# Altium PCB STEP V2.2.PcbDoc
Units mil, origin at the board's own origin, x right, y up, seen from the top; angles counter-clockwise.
Board outline 2047.24 x 720 mil, 4 copper layers (Top Layer, Signal Layer 1, Signal Layer 2, Bottom Layer), stack 30.634 mil thick; 93 components, 117 nets, 440 pads, 136 vias.
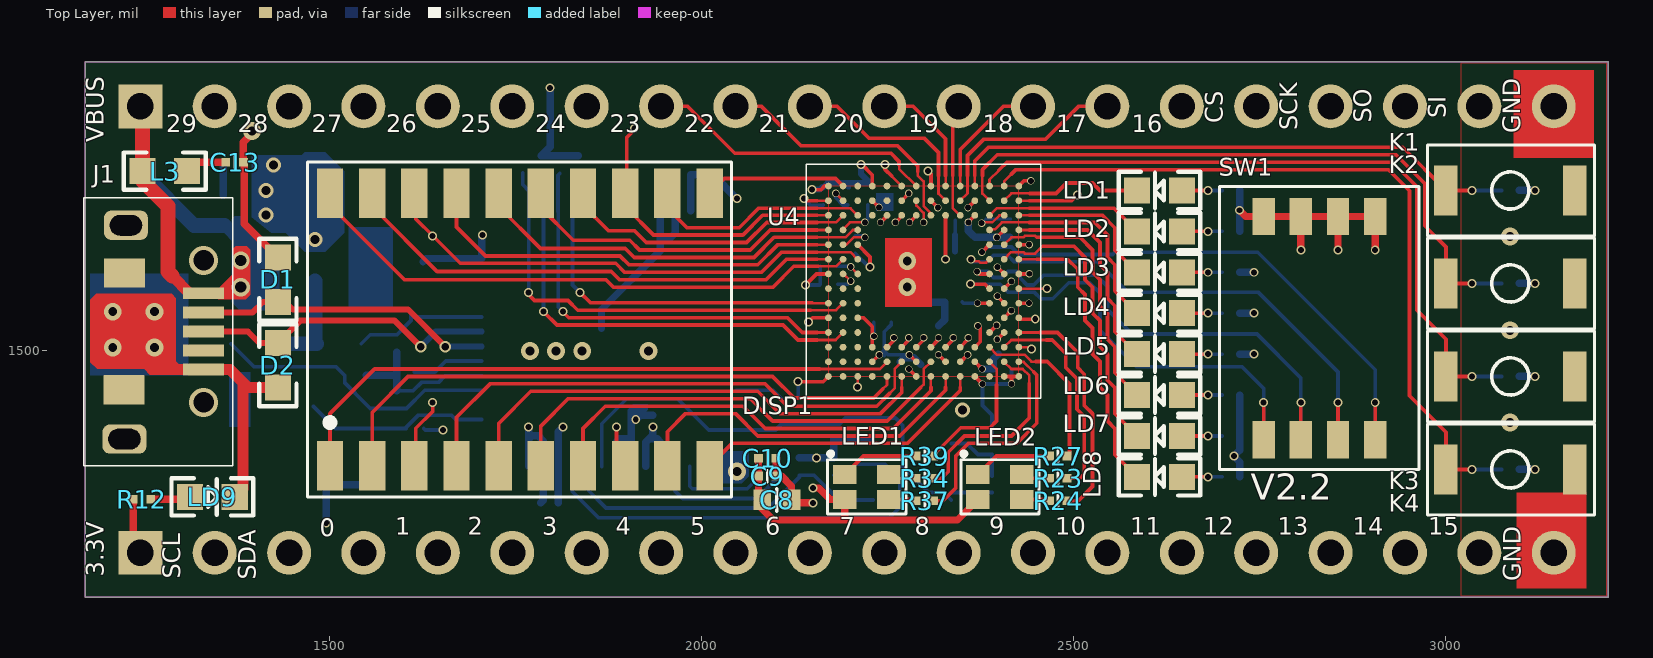
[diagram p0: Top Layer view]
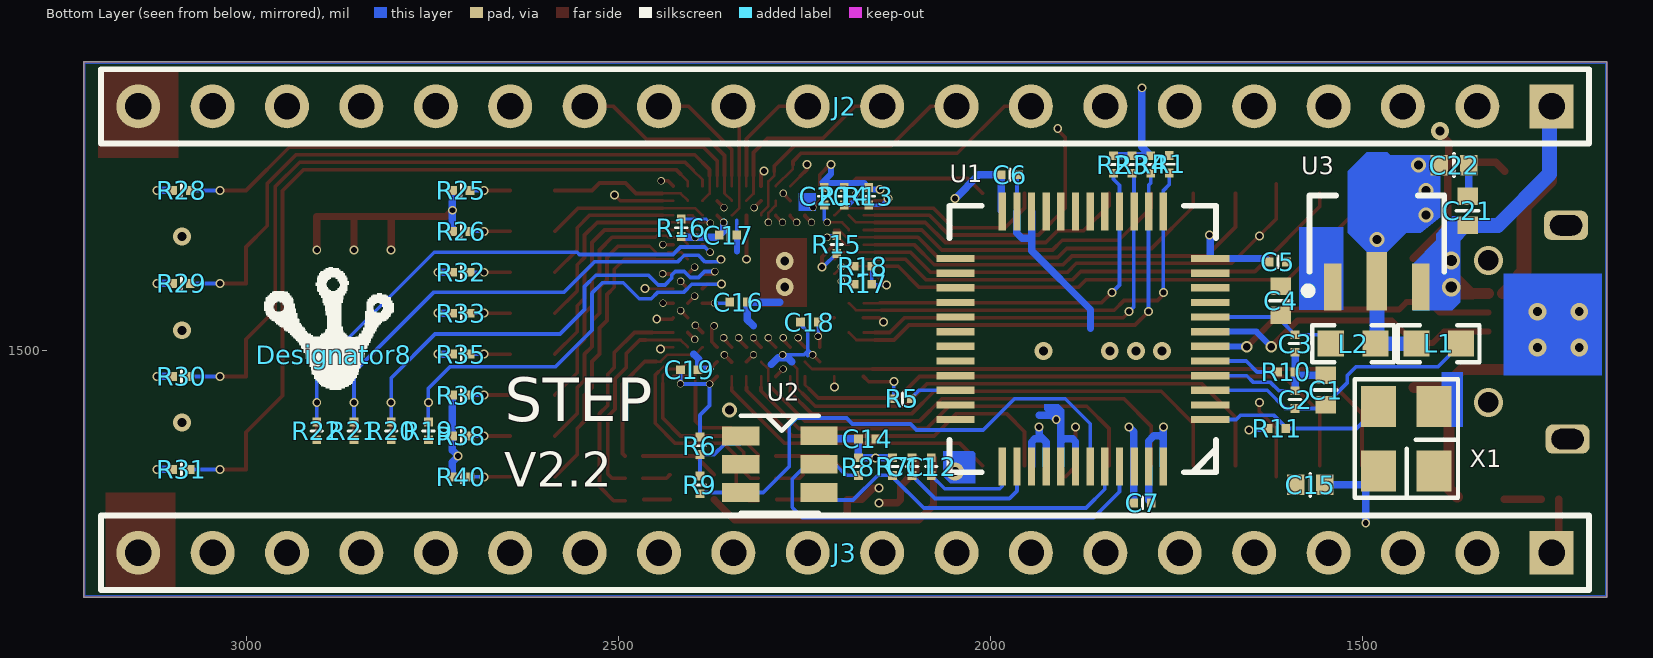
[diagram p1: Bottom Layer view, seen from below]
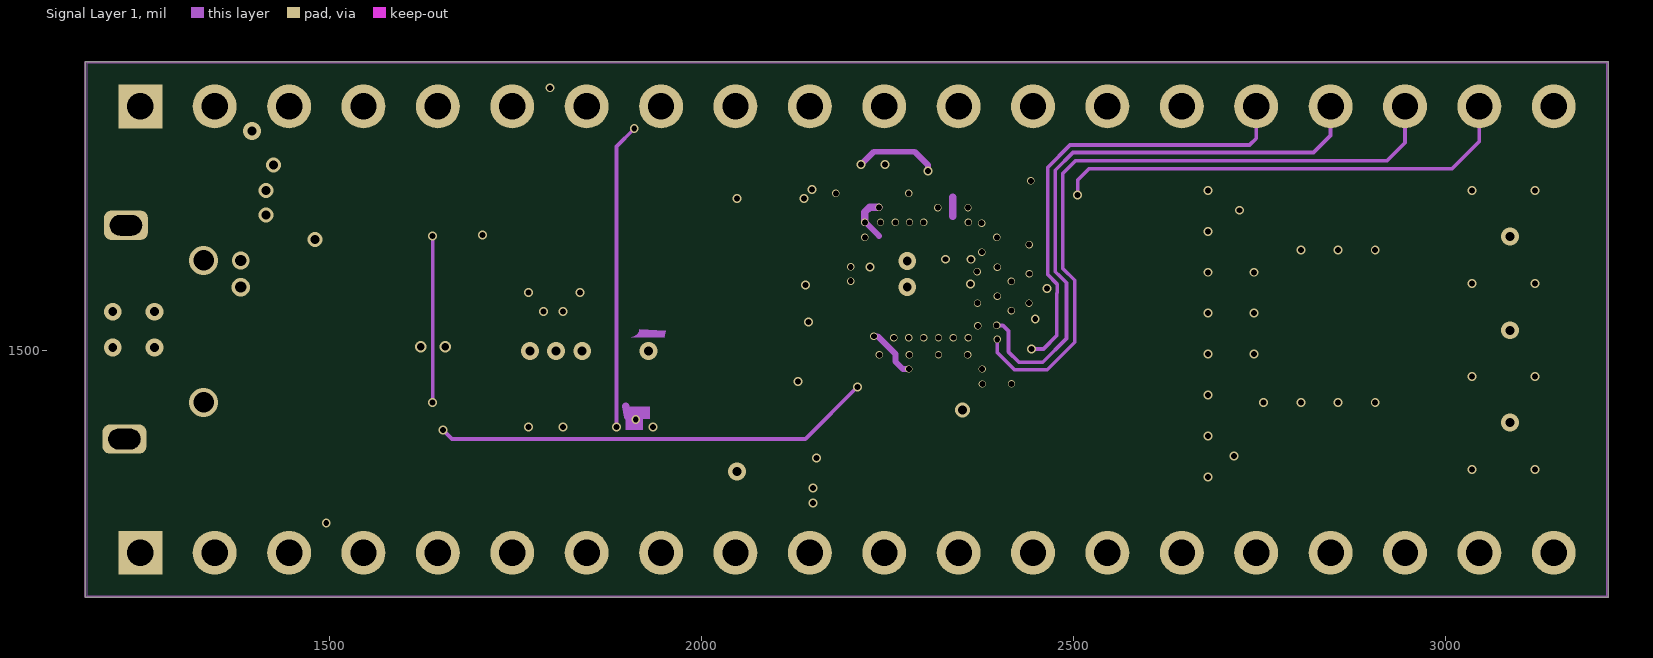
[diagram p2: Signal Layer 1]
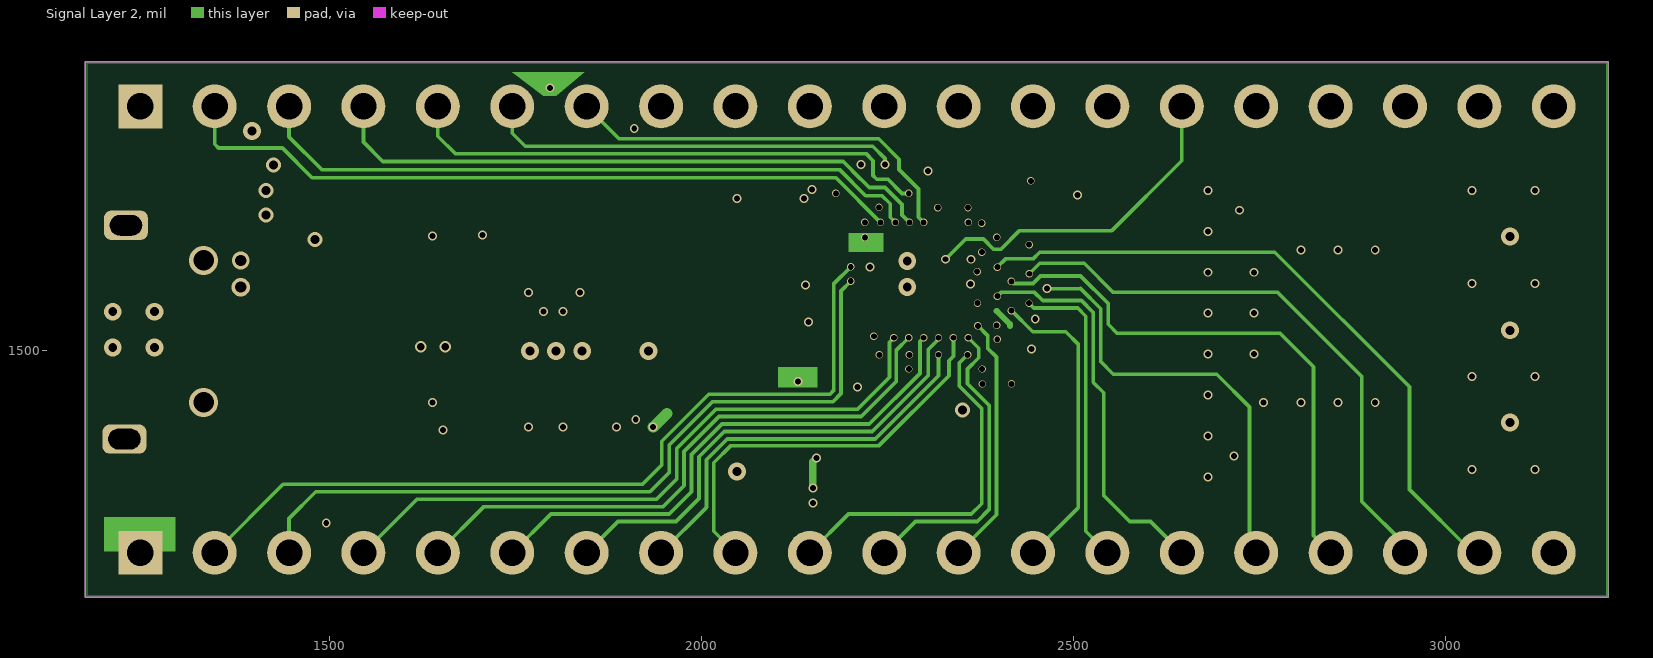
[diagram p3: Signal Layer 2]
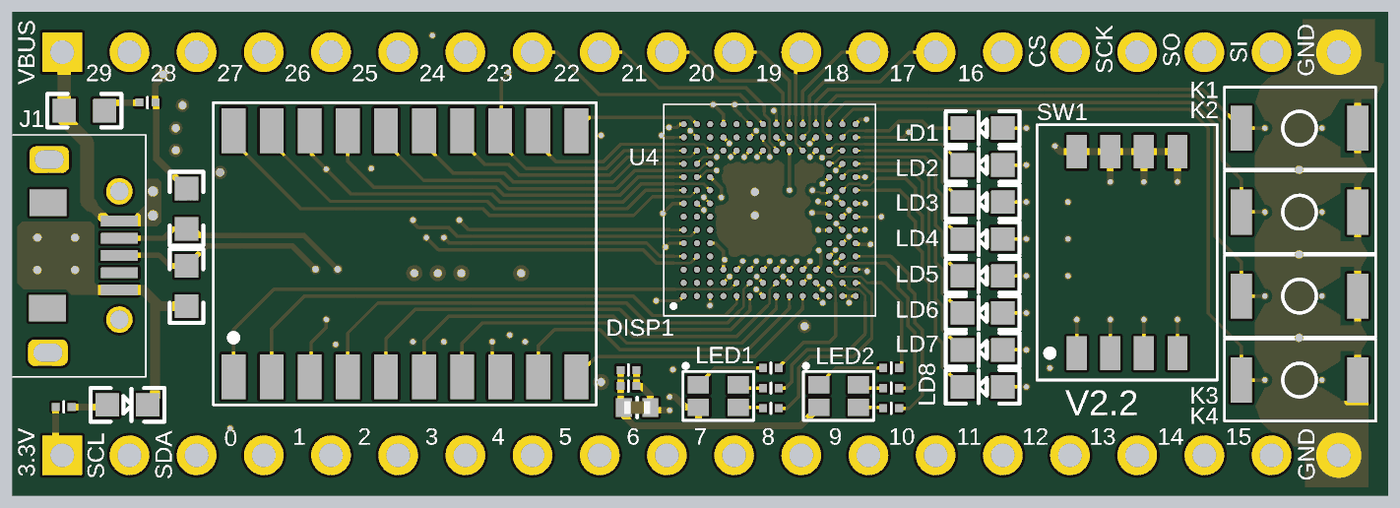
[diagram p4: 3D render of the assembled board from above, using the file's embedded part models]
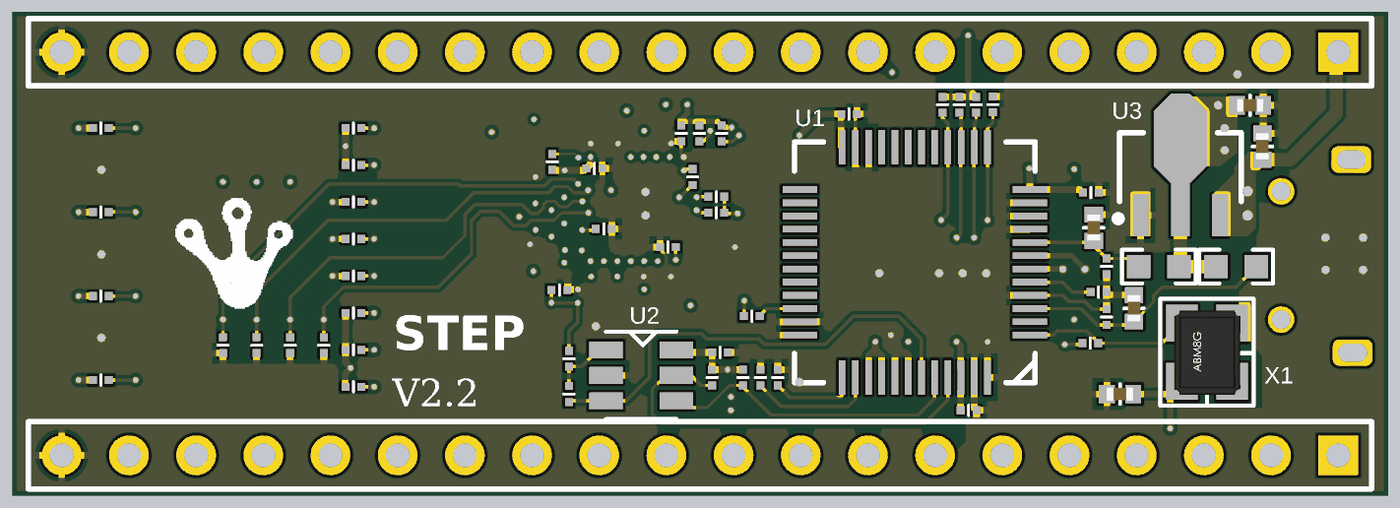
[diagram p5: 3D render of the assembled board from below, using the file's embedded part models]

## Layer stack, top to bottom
Top Solder: solder mask 0.4, Solder Resist, Dk 3.5
Top Layer: signal copper 1.4
Dielectric 1: core 10, FR-4, Dk 4.2
Signal Layer 1: signal copper 1.417
Dielectric 3: prepreg 5, Dk 4.2
Signal Layer 2: signal copper 1.417
Dielectric 2: core 10, Dk 4.2
Bottom Layer: signal copper 1.4
Bottom Solder: solder mask 0.4, Solder Resist, Dk 3.5

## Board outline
1171,1168 1171,1888 3218.24,1888 3218.24,1168

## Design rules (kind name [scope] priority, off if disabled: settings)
Clearance [All] p1: gap=3
ComponentClearance [All] p1: gap=0 collisioncheckmode=3 verticalgap=0 showdistances=FALSE
HoleToHoleClearance [All] p1: gap=8 allowstackedmicrovias=TRUE
MinimumSolderMaskSliver [All] p1: minsoldermaskwidth=0
PlaneClearance [All] p1: clearance=10
PolygonConnect PolygonConnect_1 [isvia] p1: connectstyle=Direct reliefconductorwidth=10 reliefentries=4 polygonreliefangle="90 Angle" airgapwidth=10
PolygonConnect [All] p2: connectstyle=Relief reliefconductorwidth=10 reliefentries=4 polygonreliefangle="90 Angle" airgapwidth=10
RoutingVias [All] p1: holewidth=12 width=24 viastyle="Through Hole" minholewidth=8 minwidth=10 maxholewidth=100 maxwidth=200
SilkToSilkClearance [All] p1: silktosilkclearance=0
SilkToSolderMaskClearance [IsPad] p1: minsilkscreentomaskgap=0 clearancetoexposedcopper=TRUE
SolderMaskExpansion [All] p1: expansion=4
Width [All] p1: maxlimit=100 minlimit=3 preferedwidth=5
24 further rules are at their usual default settings.

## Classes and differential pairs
component class "STEP V2.1.0": C1 C2 C3 C4 C5 C6 C7 C8 C9 C10 C11 C12 C13 C14 C15 C16 C17 C18 C19 C20 C21 C22 D1 D2 J1 L1 L2 L3 LD9 R1 R2 R3 R4 R5 R6 R7 R8 R9 R10 R11 R12 U1 U2 U3 X1
component class "STEP V2.1.1": DISP1 J2 J3 K1 K2 K3 K4 LD1 LD2 LD3 LD4 LD5 LD6 LD7 LD8 LED1 LED2 R13 R14 R15 R16 R17 R18 R19 R20 R21 R22 R23 R24 R25 R26 R27 R28 R29 R30 R31 R32 R33 R34 R35 R36 R37 R38 R39 R40 SW1 U4

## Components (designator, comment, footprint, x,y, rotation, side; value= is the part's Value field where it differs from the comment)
C1 "4.7u" C0402 1549,1427 r90 bottom
C2 "0.1u" C0201 1590,1422 r90 bottom
C3 "0.1u" C0201 1590,1521 r270 bottom
C4 "4.7u" C0402 1609,1547 r90 bottom
C5 "0.1u" C0201 1625,1619 r180 bottom
C6 "0.1u" C0201 1985,1736 r180 bottom
C7 "0.1u" C0201 1807,1295 r180 bottom
C8 "4.7u" C0402 2081,1299 r0 top
C9 "0.1u" C0201 2076,1331 r0 top
C10 "0.1u" C0201 2076,1355 r0 top
C11 "0.1u" C0201 2105,1332 r90 bottom
C12 "0.1u" C0201 2079,1332 r90 bottom
C13 "0.01u" C0201 1360,1753 r0 top
C14 "0.1u" C0201 2177,1381 r180 bottom
C15 "0.1u" C0402 1549.98,1319.17 r0 bottom
C16 "0.1u" C0201 2350,1565 r180 bottom
C17 "0.1u" C0201 2364,1655 r180 bottom
C18 "0.1u" C0201 2231,1538 r0 bottom
C19 "0.1u" C0201 2416,1474 r180 bottom
C20 "0.1u" C0201 2223,1719 r270 bottom
C21 "2.2u" C0402 1358,1668 r90 bottom
C22 "2.2u" C0402 1396,1749 r180 bottom
D1 "PGB1010603" C0603 1430,1625 r270 top
D2 "PGB1010603" C0603 1430,1450 r90 top
Designator8 "Comment" ECBC-STEP-M 2882,1494 r180 bottom
DISP1 "DISP" SMD_LED_2*8BIT_10*14 1500,1345 r0 top
J1 "MicroUSB" MICRO_USB_4 1330,1430 r90 top
J2 "Header 20" HDR1X20 1245,1828 r0 bottom
J3 "Header 20" HDR1X20 1245,1228 r0 bottom
K1 "SW-PB" SMD_KEY_3x4x2 3000,1715 r0 top
K2 "SW-PB" SMD_KEY_3x4x2 3000,1590 r0 top
K3 "SW-PB" SMD_KEY_3x4x2 3000,1465 r0 top
K4 "SW-PB" SMD_KEY_3x4x2 3000,1340 r0 top
L1 "600R,0.5A" L0603 1427,1509 r180 bottom
L2 "600R,0.5A" L0603 1542,1509 r180 bottom
L3 "600R,0.5A" L0603 1308,1741 r180 top
LD1 "Red" LED0603 2645,1715 r180 top (schematic designator LD2)
LD2 "Red" LED0603 2645,1660 r180 top (schematic designator LD3)
LD3 "Red" LED0603 2645,1605 r180 top (schematic designator LD4)
LD4 "Red" LED0603 2645,1550 r180 top (schematic designator LD5)
LD5 "Red" LED0603 2645,1495 r180 top (schematic designator LD6)
LD6 "Red" LED0603 2645,1440 r180 top (schematic designator LD7)
LD7 "Red" LED0603 2645,1385 r180 top (schematic designator LD8)
LD8 "Red" LED0603 2645,1330 r180 top (schematic designator LD9)
LD9 "Green" LED0603 1312,1303 r0 top
LED1 "RGB_LED" SMD_RGB_LED_1.5*1.6 2192,1333 r0 top
LED2 "RGB_LED" SMD_RGB_LED_1.5*1.6 2371,1333 r0 top
R1 "4K7" R0201 1759,1762 r270 bottom
R2 "10K" R0201 1834,1738 r90 bottom
R3 "10K" R0201 1809,1738 r90 bottom
R4 "10K" R0201 1784,1738 r90 bottom
R5 "10K" R0201 2106,1435 r0 bottom
R6 "10K" R0201 2390,1360 r90 bottom
R7 "10K" R0201 2131,1332 r90 bottom
R8 "10K" R0201 2177,1332 r90 bottom
R9 "4K7" R0201 2390,1331 r270 bottom
R10 "12K 1%" R0201 1590,1471 r0 bottom
R11 "33R" R0201 1626,1395 r180 bottom
R12 "1K" R0201 1259,1300 r180 top
R13 "10K" R0201 2163,1719 r270 bottom
R14 "10K" R0201 2196,1719 r270 bottom
R15 "10K" R0201 2206,1654 r270 bottom
R16 "10K" R0201 2415,1653 r90 bottom
R17 "10K" R0201 2159,1589 r0 bottom
R18 "10K" R0201 2159,1613 r0 bottom
R19 "10K" R0201 2755,1380 r90 bottom
R20 "10K" R0201 2805,1380 r90 bottom
R21 "10K" R0201 2855,1380 r90 bottom
R22 "10K" R0201 2905,1380 r90 bottom
R23 "1K" R0201 2467,1328 r0 top
R24 "1K" R0201 2467,1298 r0 top
R25 "1K" R0201 2699,1715 r0 bottom
R26 "1K" R0201 2699,1660 r0 bottom
R27 "1K" R0201 2467,1358 r0 top
R28 "10K" R0201 3075,1715 r0 bottom
R29 "10K" R0201 3075,1590 r0 bottom
R30 "10K" R0201 3075,1465 r0 bottom
R31 "10K" R0201 3075,1340 r0 bottom
R32 "1K" R0201 2699,1605 r0 bottom
R33 "1K" R0201 2699,1550 r0 bottom
R34 "1K" R0201 2288,1328 r0 top
R35 "1K" R0201 2699,1495 r0 bottom
R36 "1K" R0201 2699,1440 r0 bottom
R37 "1K" R0201 2288,1298 r0 top
R38 "1K" R0201 2699,1385 r0 bottom
R39 "1K" R0201 2288,1358 r0 top
R40 "1K" R0201 2699,1330 r0 bottom
SW1 "SPST4" SMD_KEY_4 2755,1380 r0 top
U1 "FT232HQ" LQFP9*9_48 1704,1407 r0 bottom
U2 "93LC56B" SOT-23-6 2335,1347 r270 bottom
U3 "LT1117-3.3" SOT-89-1 1480,1660 r90 bottom
U4 "LCMXO2-4000HC-4MG132" CSBGA132 2170,1465 r90 top
X1 "12MHz" SMD_CLK_2.5X3.2X0.8 1403,1338 r90 bottom

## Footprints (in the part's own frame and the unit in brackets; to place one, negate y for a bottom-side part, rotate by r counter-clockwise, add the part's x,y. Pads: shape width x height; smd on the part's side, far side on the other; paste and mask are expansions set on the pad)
C0201 [mm]
  rect 0.3x0.3 smd: 1(0,0) 2(0.6,0)
  silkscreen extent 0.3,-0.2 0.3,0.2, body extent 0,-0.15 0.6,0.15, height 0.31
C0402 [mm]
  rect 0.6x0.7 smd: 1(0,0) 2(1,0)
  silkscreen extent 0.5,-0.38 0.5,0.38, body extent 0.01,-0.25 1.01,0.25, height 0.5
C0603 [mil]
  rect 35x35 smd: 1(0,0) 2(60,0)
  silkscreen extent -25,-25 85,25, body extent -1,-16 61,16, height 24
CSBGA132 [mm]
  round 0.23 smd mask+0.051: A1(0,0) A2(0.5,0) A3(1,0) A4(1.5,0) A5(2,0) A6(2.5,0) A7(3,0) A8(3.5,0) A9(4,0) A10(4.5,0) A11(5,0) A12(5.5,0) A13(6,0) A14(6.5,0) B1(0,-0.5) B2(0.5,-0.5) B3(1,-0.5) B4(1.5,-0.5) B5(2,-0.5) B6(2.5,-0.5) B7(3,-0.5) B8(3.5,-0.5) B9(4,-0.5) B10(4.5,-0.5) B11(5,-0.5) B12(5.5,-0.5) B13(6,-0.5) B14(6.5,-0.5) C1(0,-1) C2(0.5,-1) C3(1,-1) C4(1.5,-1) C5(2,-1) C6(2.5,-1) C7(3,-1) C8(3.5,-1) C9(4,-1) C10(4.5,-1) C11(5,-1) C12(5.5,-1) C13(6,-1) C14(6.5,-1) D1(0,-1.5) D2(0.5,-1.5) D3(1,-1.5) D12(5.5,-1.5) D13(6,-1.5) D14(6.5,-1.5) E1(0,-2) E2(0.5,-2) E3(1,-2) E12(5.5,-2) E13(6,-2) E14(6.5,-2) F1(0,-2.5) F2(0.5,-2.5) F3(1,-2.5) F12(5.5,-2.5) F13(6,-2.5) F14(6.5,-2.5) G1(0,-3) G2(0.5,-3) G3(1,-3) G12(5.5,-3) G13(6,-3) G14(6.5,-3) H1(0,-3.5) H2(0.5,-3.5) H3(1,-3.5) H12(5.5,-3.5) H13(6,-3.5) H14(6.5,-3.5) J1(0,-4) J2(0.5,-4) J3(1,-4) J12(5.5,-4) J13(6,-4) J14(6.5,-4) K1(0,-4.5) K2(0.5,-4.5) K3(1,-4.5) K12(5.5,-4.5) K13(6,-4.5) K14(6.5,-4.5) L1(0,-5) L2(0.5,-5) L3(1,-5) L12(5.5,-5) L13(6,-5) L14(6.5,-5) M1(0,-5.5) M2(0.5,-5.5) M3(1,-5.5) M4(1.5,-5.5) M5(2,-5.5) M6(2.5,-5.5) M7(3,-5.5) M8(3.5,-5.5) M9(4,-5.5) M10(4.5,-5.5) M11(5,-5.5) M12(5.5,-5.5) M13(6,-5.5) M14(6.5,-5.5) N1(0,-6) N2(0.5,-6) N3(1,-6) N4(1.5,-6) N5(2,-6) N6(2.5,-6) N7(3,-6) N8(3.5,-6) N9(4,-6) N10(4.5,-6) N11(5,-6) N12(5.5,-6) N13(6,-6) N14(6.5,-6) P1(0,-6.5) P2(0.5,-6.5) P3(1,-6.5) P4(1.5,-6.5) P5(2,-6.5) P6(2.5,-6.5) P7(3,-6.5) P8(3.5,-6.5) P9(4,-6.5) P10(4.5,-6.5) P11(5,-6.5) P12(5.5,-6.5) P13(6,-6.5) P14(6.5,-6.5)
  round 0.3 on Top Overlay mask+0.051: A3(-0.381,0.381)
  silkscreen extent -0.75,-7.25 7.25,0.75
ECBC-STEP-M [mil] "height=165mil"
  silkscreen extent -94,-47 81,117
HDR1X20 [mm] "Connector; Header; 20 Position"
  rect 1.5x1.5 hole 0.9: 1(0,0)
  round 1.5 hole 0.9: 2(2.54,0) 3(5.08,0) 4(7.62,0) 5(10.16,0) 6(12.7,0) 7(15.24,0) 8(17.78,0) 9(20.32,0) 10(22.86,0) 11(25.4,0) 12(27.94,0) 13(30.48,0) 14(33.02,0) 15(35.56,0) 16(38.1,0) 17(40.64,0) 18(43.18,0) 19(45.72,0) 20(48.26,0)
  silkscreen extent -1.27,-1.27 49.53,1.27
L0603 [mil]
  rect 35x35 smd: 1(0,0) 2(60,0)
  silkscreen extent -25,-25 85,25, body extent -1,-16 61,16, height 35
LED0603 [mil]
  rect 35x35 smd: 1(0,0) 2(60,0)
  silkscreen extent -25,-25 85,25, body extent -3,-18 64,18, height 35
LQFP9*9_48 [mm]
  rect 1.3x0.25 smd: 1(0,0) 2(0,-0.5) 3(0,-1) 4(0,-1.5) 5(0,-2) 6(0,-2.5) 7(0,-3) 8(0,-3.5) 9(0,-4) 10(0,-4.5) 11(0,-5) 12(0,-5.5) 25(8.7,-5.5) 26(8.7,-5) 27(8.7,-4.5) 28(8.7,-4) 29(8.7,-3.5) 30(8.7,-3) 31(8.7,-2.5) 32(8.7,-2) 33(8.7,-1.5) 34(8.7,-1) 35(8.7,-0.5) 36(8.7,0)
  rect 0.25x1.3 smd: 13(1.6,-7.1) 14(2.1,-7.1) 15(2.6,-7.1) 16(3.1,-7.1) 17(3.6,-7.1) 18(4.1,-7.1) 19(4.6,-7.1) 20(5.1,-7.1) 21(5.6,-7.1) 22(6.1,-7.1) 23(6.6,-7.1) 24(7.1,-7.1) 37(7.1,1.6) 38(6.6,1.6) 39(6.1,1.6) 40(5.6,1.6) 41(5.1,1.6) 42(4.6,1.6) 43(4.1,1.6) 44(3.6,1.6) 45(3.1,1.6) 46(2.6,1.6) 47(2.1,1.6) 48(1.6,1.6)
  silkscreen extent -0.2,-7.3 8.9,1.8, body extent -0.16,-7.24 8.84,1.76, height 1.44
MICRO_USB_4 [mm]
  rect 0.4x1.4 smd: 1(3.725,0) 2(3.075,0) 3(2.425,0) 4(1.775,0) 5(1.125,0)
  rrect50% 1x1.5 hole 0.7 slot 1.1 at 90 deg: ""(-1.251,2.701) ""(6.05,2.65)
  rect 1x1.4 smd: ""(0.432,2.718) ""(4.42,2.692)
  silkscreen extent -2.16,-1 6.98,4.09, body extent -1.69,-0.15 6.51,5.28, height 2.73
R0201 [mm]
  rect 0.3x0.3 smd: 1(0,0) 2(0.6,0)
  silkscreen extent 0.3,-0.2 0.3,0.2, body extent -0.04,-0.16 0.64,0.17, height 0.34
SMD_CLK_2.5X3.2X0.8 [mm]
  rect 1.4x1.2 smd: 1(0,0) 2(2.2,0) 3(2.2,1.9) 4(0,1.9)
  silkscreen extent -0.91,-0.81 3.12,2.72, body extent -0.51,-0.31 2.69,2.19, height 1.01
SMD_KEY_3x4x2 [mm]
  rect 0.8x1.7 smd: 1(0,0) 2(4.4,0)
  silkscreen extent -0.64,-1.55 5.08,1.55
SMD_KEY_4 [mm]
  rect 0.76x1.27 smd: 1(0,0) 2(1.27,0) 3(2.54,0) 4(3.81,0) 5(3.81,7.62) 6(2.54,7.62) 7(1.27,7.62) 8(0,7.62)
  round 0.5 on Top Overlay: 9(-1.016,0)
  silkscreen extent -1.5,-1.02 5.31,8.64
SMD_LED_2*8BIT_10*14 [mm]
  rect 0.9x1.7 smd: 1(0,0) 2(1.44,0) 3(2.88,0) 4(4.32,0) 5(5.76,0) 6(7.2,0) 7(8.64,0) 8(10.08,0) 9(11.52,0) 10(12.96,0) 11(12.96,9.3) 12(11.52,9.3) 13(10.08,9.3) 14(8.64,9.3) 15(7.2,9.3) 16(5.76,9.3) 17(4.32,9.3) 18(2.88,9.3) 19(1.44,9.3) 20(0,9.3)
  silkscreen extent -0.76,-1.06 13.72,10.37, body extent -0.57,-0.35 13.53,9.65, height 3
SMD_RGB_LED_1.5*1.6 [mm]
  rect 0.8x0.65 smd: 1(0,0) 2(1.5,0) 3(0,-0.85) 4(1.5,-0.85)
  silkscreen extent -0.58,-1.35 2.08,0.74
SOT-23-6 [mil]
  rect 25x50 smd: 1(-37.99,0) 2(0,0) 3(38,0) 4(38,105) 5(0,105) 6(-38,105)
  silkscreen extent -65,0 65,105, body extent -57,-2 57,108, height 57
SOT-89-1 [mm] "SOT89, 3-Leads, Body 4.50x2.45mm, Pitch 1.50mm, Lead Span 4.1mm, IPC Low Density"
  rect 1.6x0.6 smd: 1(-1.9,1.5) 3(-1.9,-1.5)
  rect 2x0.7 smd: 2(-1.7,0)
  Top Layer region: -0.7,0.35 -0.05,1 2.05,1 2.7,0.35 2.7,-0.35 2.05,-1 -0.05,-1 -0.7,-0.35
  silkscreen extent -2.15,-2.3 1.22,2.48, body extent -1.38,-2.3 1.22,2.3, height 1.6

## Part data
C1 C4 C8: library part "Cap_non polar", "多层陶瓷电容器MLCC - SMD/SMT 4.7uF 6.3V 10%"
C2 C3 C5 C6 C7 C9 C10 C11 C12 C13 C14 C15 C16 C17 C18 C19 C20 C21 C22: library part "Cap_non polar", "多层陶瓷电容器MLCC - SMD/SMT 0603 xxF 50volts C0G 5%"
D1 D2: "ESD 抑制器 0603 24VDC .06pF"
DISP1: "Seven Segment Display,Double"
J1: library part "Micro USB Header", "Micro USB Header"
J2 J3: "Header, 20-Pin"
K1 K2 K3 K4: "Switch"
L1 L2 L3: library part BLM18AG601SN1D, "EMI滤波珠子、芯片与阵列 0603 600 OHM"
LD1 LD2 LD3 LD4 LD5 LD6 LD7 LD8 LD9: library part LED, "Typical INFRARED GaAs LED,1.8V,10mA,Red"
LED1 LED2: library part SMD_RGB_LED_1.5*1.6, "SMD_RGB_LED_1.5*1.6"
R1 R2 R3 R4 R5 R6 R7 R8 R9 R10 R11 R12 R13 R14 R15 R16 R17 R18 R19 R20 R21 R22 R23 R24 R25 R26 R27 R28 R29 R30 R31 R32 R33 R34 R35 R36 R37 R38 R39 R40: library part Res, "厚膜电阻器 - SMD xx OHM 5%"
SW1: "贴片拨码开关 1.27MM间距 4位贴片平拨开关 4PIN"
U1: "USB 接口集成电路 USB HS to UART/FIFO SPI/JTAG/I2C QFN-48"
U2: "电可擦除可编程只读存储器 128x16"
U3: library part LTC1117-x, "LDO,5.5V to 3.3V"
U4: "IC,LCMXO2-4000HC-4MG132 FPGA,csBGA132,4320 LUTs"
X1: library part "Active Crystal", "SiTime Oscillator,12MHZ SMD,2.0mm x 1.6mm"

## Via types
v1: diameter 12, hole 8, Top Layer to Bottom Layer, tented both sides, 65 vias
v2: diameter 10, hole 8, Top Layer to Bottom Layer, tented both sides, 45 vias
v3: diameter 24, hole 12, Top Layer to Bottom Layer, tented both sides, 15 vias
v4: diameter 20, hole 12, Top Layer to Bottom Layer, tented both sides, 5 vias
v5: diameter 39.37, hole 27.56, Top Layer to Bottom Layer, 2 vias
v6: diameter 15, hole 10, Top Layer to Bottom Layer, tented both sides, 2 vias
v7: diameter 24, hole 15, Top Layer to Bottom Layer, tented both sides, 1 vias
v8: diameter 25, hole 15, Top Layer to Bottom Layer, tented both sides, 1 vias

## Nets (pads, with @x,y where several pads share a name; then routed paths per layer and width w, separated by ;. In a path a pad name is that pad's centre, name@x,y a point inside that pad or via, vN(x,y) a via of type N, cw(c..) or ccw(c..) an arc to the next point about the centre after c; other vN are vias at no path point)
+3.3V: C5.1 C6.1 C7.1 C8.1 C9.1 C10.1 C14.1 C15.1 C16.1 C17.1 C18.1 C19.1 C20.1 C22.1 J3.1 L1.1 L2.2 LED1.3 LED2.3 R2.2 R3.2 R4.2 R5.2 R6.2 R7.2 R8.2 R12.2 R13.1 R14.1 R15.1 R16.1 R17.1 R18.1 R25.2 R26.2 R28.2 R29.2 R30.2 R31.2 R32.2 R33.2 R35.2 R36.2 R38.2 R40.2 SW1.5 SW1.6 SW1.7 SW1.8 U1.12 U1.24 U1.39 U1.40 U1.46 U2.6 U3.2 U4.A1 U4.A8 U4.A14 U4.B10 U4.C5 U4.D3 U4.D14 U4.G1 U4.H14 U4.L1 U4.L12 U4.M6 U4.N1 U4.N11 U4.P1 U4.P14 X1.4 | length 3199.4
  Top Layer w3.5: U4.B10 2194.17,1642.17 2204,1652 v2(2219,1652)
  Top Layer w5: v1(2129,1458) 2163,1458 U4.A1 ; v1(2139,1588) 2153.8,1602.8 U4.A8 ; v1(2148,1716) 2160,1716 2164.91,1720.91 U4.A14 ; U4.C5 2217.26,1543.74 2229.06,1531.94 U4.D3 ; v1(2214,1750) 2215,1750 2229.06,1735.94 U4.D14 ; v2(2278.11,1475) U4.G1 ; v1(2304,1741) 2307.8,1737.2 U4.H14 ; v2(2358,1672) 2358,1672.68 U4.L12 ; U4.L1 v2(2377,1454.85) ; v2(2370.43,1563.43) U4.M6 ; v2(2396.37,1652) U4.N11 ; U4.N1 2416.06,1465 ; v2(2416.06,1455.06) 2416.06,1465 ; U4.P1 2416.06,1465 ; U4.P14 2433,1728 v2(2442,1728)
  Top Layer w10: R12.2 1235.38,1237.62 J3.1 ; C10.1 C9.1 2076,1292 2096,1272 2192,1272 ; v1(2149,1315) 2157,1315 2172.46,1299.54 LED1.3 2192,1272 ; LED2.3 2343.46,1272 2192,1272 ; v1(2722.62,1688.38) 2731,1680 SW1.8 SW1.7 ; v1(2805,1635) SW1.7 ; v1(2855,1635) SW1.6 ; v1(2905,1635) SW1.5 SW1.6 ; SW1.7 SW1.6
  Signal Layer 1 w8: v1(2214,1750) 2231,1767 2286,1767 2304,1749 v1(2304,1741) ; v2(2231,1519) 2236.2,1519 2259.87,1495.34 2259.87,1485.13 2270,1475 v2(2278.11,1475)
  Signal Layer 2 w8: 2396,1553 2396.32,1553 2414,1535.32 2414,1533
  Signal Layer 2 w10: v1(2149,1315) 2149,1350.62 v1(2154,1355.62)
  Signal Layer 2 w15: v1(1934,1397) 1935,1397 1953,1415
  Bottom Layer w5: R5.2 v1@2129.62,1457.38 ; v1(2139,1588) 2158,1588 R17.1 R18.1 ; R14.1 R14.1@2198,1719 ; R15.1 2217,1654 v2(2219,1652) ; v2(2231,1519) C18.1 ; C16.1 2351.57,1563.43 v2(2370.43,1563.43) ; R6.2 2390,1413 2377,1426 v2(2377,1454.85) v2@2415.85,1454.85 ; v2@2416,1455.13 C19.1
  Bottom Layer w8: v1(2148,1716) 2158,1716 R13.1@2162,1720 ; R13.1 2169,1725 2224,1725 2225,1726 2214,1737 v1(2214,1750)
  Bottom Layer w10: v1(1495,1268) 1495,1318.17 1496,1319.17 C15.1 ; C5.1 1629.54,1623.54 U1.12 1704,1654 v1(1705,1655) ; v1(1796,1853) 1796,1773.62 R4.2 R3.2 R2.2 ; C7.1 1807,1391 v1(1813,1397) ; U1.40 1924.47,1376.47 1929,1381 ; v1(1934,1397) 1934,1386 1929,1381 ; U1.39 1944.16,1376.84 1940,1381 1929,1381 ; U1.24@1985,1688 C6.1 2015,1736 v1(2047,1704) ; R7.2 v1(2154,1355.62) R8.2 C14.1 U2.6@2224,1381 ; v2(2358,1672) 2358,1661 C17.1 2367,1652 v2(2396.37,1652) R16.1@2414,1652 ; 2722.62,1412.62 R38.2 2722.62,1365.62 v1(2715,1358) 2723,1350 R40.2@2723,1330.38 ; 2722.62,1413.38 R36.2 ; R35.2 v1(2742,1495) ; R33.2 v1(2742,1550) ; R32.2 v1(2742,1605) ; R26.2 v1(2722.62,1688.38) R25.2 ; R31.2 v1(3120,1340) ; R30.2 v1(3120,1465) ; R29.2 v1(3120,1590) ; R28.2 v1(3120,1715)
  Bottom Layer w20: L1.1@1434,1508 1435,1509 L2.2 ; L2.2@1480,1511 U3.2
  other v4: 1480,1649 1414,1682 1414,1715 1424,1749
B_LED1: R37.2 U4.P2 | length 303.1
  Top Layer w3.5: U4.P2 2432.32,1484.68 2446,1471
  Top Layer w5: R37.2 2324,1298 2341,1315 2341,1358 2358,1375 2423,1375 2450,1402 2450,1467 2446,1471
B_LED2: R24.2 U4.P4 | length 320.9
  Top Layer w3.5: U4.P4 2453.94,1524.06
  Top Layer w5: 2453.94,1524.06 2478.09,1524.06 2505,1497.14 2505,1477 2514,1468 2514,1426 2525,1415 2525,1317 2506,1298 R24.2
CLK: R11.2 U1.1 X1.3 | length 249.8
  Bottom Layer w5: X1.3 1507.42,1395 R11.2@1601,1395 ; R11.2 R11.2@1601,1395 ; U1.1 1669,1407 1663,1413 1619,1413 R11.2@1601,1395
DONE: R13.2 U4.A13 | length 63.9
  Top Layer w3.5: 2155,1701.22 U4.A13
  Top Layer w5: v1(2137,1704) 2140,1701 2154.78,1701
  Bottom Layer w5: v1(2137,1704) 2146,1695 2162.62,1695 R13.2
G_LED1: R34.2 U4.N2 | length 275.7
  Top Layer w3.5: U4.N2 2415.91,1475 2431,1475 2440,1466 2440,1456
  Top Layer w5: R34.2 2322,1328 2331,1337 2331,1363 2353,1385 2416,1385 2440,1409 2440,1456
G_LED2: R23.2 U4.N3 | length 292.4
  Top Layer w3.5: U4.N3 2415.85,1514 2463,1514
  Top Layer w5: 2463,1514 2471,1514 2489,1496 2489,1477 2504,1462 2504,1421 2514,1411 2514,1334 2508,1328 R23.2
GND: C1.2 C2.2 C3.2 C4.2 C5.2 C6.2 C7.2 C8.2 C9.2 C10.2 C11.2 C12.2 C13.2 C14.2 C15.2 C16.2 C17.2 C18.2 C19.2 C20.2 C21.2 C22.2 D1.1 D2.1 J1.5 J2.20 J3.20 K1.2 K2.2 K3.2 K4.2 LD9.2 R1.1 R10.1 R19.1 R20.1 R21.1 R22.1 U1.4 U1.9 U1.10 U1.11 U1.22 U1.23 U1.35 U1.36 U1.41 U1.42 U1.47 U1.48 U2.2 U3.1 U4.A5 U4.B11 U4.D2 U4.D13 U4.G2 U4.H13 U4.L2 U4.L13 U4.P5 U4.P10 X1.2 | length 2116.4
  Top Layer w3.5: U4.B11 2189.68,1662.68 2199,1672 v2(2219,1672)
  Top Layer w5: v1(2143,1538) 2148.74,1543.74 U4.A5 ; U4.D2 v2(2238.37,1494) ; U4.D13 v2(2238,1692.28) ; v2(2278.8,1494) U4.G2 ; U4.H13 v2(2317,1692) ; v2(2357.63,1692) U4.L13 ; U4.L2 v2(2376.54,1475) ; U4.P5 2427.65,1542 v1(2448,1542) ; U4.P10 v2(2439.83,1642.17)
  Top Layer w10: C13.2 1383.62,1779.62 1395,1791 v3(1395,1795) ; C13.2@1385,1753 1385,1670 D1.1 D1.1@1431,1624 ; C10.2 C9.2 2107,1331 2120.37,1317.63 C8.2 2124.37,1295 v1(2149,1295)
  Top Layer w15: 1286,1482 1293.71,1474.29 J1.5 1365.71,1474.29 1383,1457 ; LD9.2 1383,1314 1383,1457 ; D2.1 1390,1450 1383,1457
  Signal Layer 1 w8: v2@2220,1672 2238,1654
  Signal Layer 1 w10: 1897.5,1424.86 1900,1411 v1(1911,1407) ; v2(2219,1672) 2219,1686 2225.28,1692.28 v2(2238,1692.28) ; 2337,1680 2337,1706
  Bottom Layer w5: C2.2 1611.62,1445.62 1623,1457 1646,1457 1655.06,1466.06 U1.4 ; C6.2 1963.84,1733.54 U1.23 ; v2(2219,1672) 2223,1676 C20.2 ; v2(2238.37,1494) 2245,1500.63 2245,1525 2254.62,1534.62 C18.2 ; 2245,1493 2245,1499 2250,1494 v2(2278.8,1494) ; C17.2 2340.38,1674.75
  Bottom Layer w8: 2340.38,1632.87 C17.2
  Bottom Layer w10: C21.2@1356.63,1708.74 C22.2 ; U3.1@1538,1586.25 1537,1587.25 1539,1589.25 1539,1637 ; C1.2 R10.1@1585.37,1466.37 ; C2.2 R10.1 C3.2 ; U1.48 1766.99,1380.99 ; v1(1766.99,1396.99) 1766.99,1380.99 ; C7.2 1786.68,1298.3 U1.47 1787,1344.33 1787,1378 1780,1385 1771,1385 1766.99,1380.99 ; 1865,1530 1865,1555 1944.16,1634.16 1944.16,1651 ; U1.42 1885.1,1377.1 1889,1381 1901,1381 1904.79,1377.21 ; U1.41 1904.79,1377.21 ; 1934,1413 1917,1413 v1(1911,1407) 1911,1408 1904.79,1401.79 1904.79,1377.21 ; U1.22 1944.16,1651 ; U1.23 1963.84,1657.84 1957,1651 1944.16,1651 ; 2266.53,1484.63 2271.9,1490 2285,1490 2294,1481 ; 2282.44,1565 C16.2 2326.38,1541.38 2318,1533 ; v2(2376.54,1475) 2391.38,1475 2391.38,1488.38 2398,1495
  other v3: 2047,1337 3086,1403 1769,1499 1804,1499 1839,1499 1928,1499 1208,1504 1264,1504 3086,1527 1208,1552 1264,1552 2276,1585 2276,1620 3086,1653
  other v4: 2350,1420
GPIO0: J3.4 U4.E3 | length 900.7
  Top Layer w5: U4.E3 2258,1513.63 v2(2258,1517)
  Signal Layer 2 w5: J3.4 1617,1300 1939,1300 1966,1327 1966,1368 2019,1421 2209,1421 2252,1464 2252,1511 v2(2258,1517)
GPIO1: J3.5 U4.F3 | length 820.9
  Top Layer w5: U4.F3 2278,1513.94 v2(2278,1517)
  Signal Layer 2 w5: J3.5 1707,1290 1948,1290 1976,1318 1976,1364 2023,1411 2214,1411 2261,1458 2261,1500 v2(2278,1517)
GPIO2: J3.6 U4.G3 | length 743.9
  Top Layer w5: U4.G3 2298,1514.26 v2(2298,1517)
  Signal Layer 2 w5: J3.6 1797,1280 1956,1280 1986,1310 1986,1360 2027,1401 2225,1401 2293,1469 2293,1512 v2(2298,1517)
GPIO3: J3.7 U4.H3 | length 664
  Top Layer w5: U4.H3 2318,1514.57 v2(2318,1517)
  Signal Layer 2 w5: J3.7 1887,1270 1965,1270 1996,1301 1996,1357 2030,1391 2229,1391 2304,1466 2304,1501 2318,1515 v2(2318,1517)
GPIO4: J3.8 U4.J2 | length 550.6
  Top Layer w5: v2(2318,1494.17) U4.J2
  Signal Layer 2 w5: J3.8 2006,1289 2006,1353 2034,1381 2233,1381 2318,1466 v2(2318,1494.17)
GPIO5: J3.9 U4.J3 | length 567.9
  Top Layer w5: U4.J3 2338,1514.89 v2(2338,1517)
  Signal Layer 2 w5: J3.9 2016,1257 2016,1349 2039,1372 2238,1372 2332,1466 2332,1486 2338,1492 v2(2338,1517)
GPIO6: J3.10 U4.K2 | length 489.2
  Top Layer w5: U4.K2 2347.43,1484.43 v2(2357,1494)
  Signal Layer 2 w5: J3.10 2197,1280 2362,1280 2376,1294 2376,1422 2346,1452 2346,1483 v2(2357,1494)
GPIO7: J3.11 U4.K3 | length 437.2
  Top Layer w5: U4.K3 2358,1515.2 v2(2358,1517)
  Signal Layer 2 w5: J3.11 2287,1270 2370,1270 2386,1286 2386,1426.14 2357,1455.14 2357,1475 2372,1490 2372,1503 v2(2358,1517)
GPIO8: J3.12 U4.L3 | length 369.3
  Top Layer w5: U4.L3 2374,1511.52 2374,1530 v2(2371,1533)
  Signal Layer 2 w5: J3.12 2396,1279 2396,1491 2384,1503 2384,1520 v2(2371,1533)
GPIO9: J3.13 U4.N5 | length 428
  Top Layer w5: U4.N5 v2(2416,1553.52)
  Signal Layer 2 w5: v2(2416,1553.52) 2444.52,1525 2489,1525 2506,1508 2506,1289 J3.13
GPIO10: J3.14 U4.P6 | length 427.3
  Top Layer w5: U4.P6 v2(2439.57,1563.43)
  Signal Layer 2 w5: v2(2439.57,1563.43) 2446,1557 2505,1557 2516,1546 2516,1257 J3.14
GPIO11: J3.15 U4.N6 | length 544.3
  Top Layer w3.5: v2@2397,1572.65 v2(2397,1573)
  Top Layer w5: v2@2397,1572.65 U4.N6
  Signal Layer 2 w5: v2(2397,1573) 2402,1578 2447,1578 2458,1567 2510,1567 2526,1551 2526,1457 2540,1443 2540,1305 2575,1270 2603,1270 J3.15
GPIO12: J3.16 U4.P7 | length 617.4
  Top Layer w3.5: U4.P7 2426.02,1583 v1(2464,1583)
  Signal Layer 2 w5: v1(2464,1583) 2508.78,1583 2508.89,1583.11 2536,1556 2536,1485 2553,1468 2692,1468 2736,1424 2736,1237 J3.16
GPIO13: J3.17 U4.N7 | length 751.6
  Top Layer w5: U4.N7 v2(2416,1592.89)
  Signal Layer 2 w5: v2(2416,1592.89) 2418.89,1590 2445,1590 2455,1600 2509,1600 2546,1563 2546,1535 2558,1523 2777,1523 2822,1478 2822,1251 J3.17
GPIO14: J3.18 U4.P8 | length 790.9
  Top Layer w3.5: v2@2439.8,1603 v2(2440,1603)
  Top Layer w5: U4.P8 v2@2439.8,1602.8
  Signal Layer 2 w5: v2(2440,1603) 2454,1617 2514,1617 2553,1578 2774,1578 2887,1465 2887,1297 2945,1239 J3.18
GPIO15: J3.19 U4.N8 | length 917.5
  Top Layer w5: v2(2397,1612) U4.N8
  Signal Layer 2 w5: v2(2397,1612) 2408,1623 2445,1623 2454,1632 2770,1632 2951,1451 2951,1313 3036,1228 J3.19
GPIO16: J2.15 U4.J12 | length 515.8
  Top Layer w5: v1(2327.48,1622.52) U4.J12
  Signal Layer 2 w5: v1(2327.48,1622.52) 2354.67,1649.71 2378.29,1649.71 2392,1636 2402,1636 2427,1661 2551,1661 2645,1755 J2.15
GPIO17: J2.14 U4.K13 | length 280.2
  Top Layer w3.5: U4.K13 2357,1711.06 2357,1735
  Top Layer w5: 2357,1735 2357,1762 2379,1784 2462,1784 2506,1828 J2.14
GPIO18: J2.13 U4.K14 | length 171.1
  Top Layer w3.5: U4.K14 2347.17,1735
  Top Layer w5: 2347.17,1735 2347.17,1770.17 2405,1828 J2.13
GPIO19: J2.12 U4.K12 | length 154
  Top Layer w3.5: 2337,1735 2337,1691.7 U4.K12
  Top Layer w5: 2337,1735 2337,1820 J2.12
GPIO20: J2.11 U4.J14 | length 164.1
  Top Layer w3.5: U4.J14 2327.48,1735
  Top Layer w5: J2.11 2284,1828 2327.48,1784.52 2327.48,1735
GPIO21: J2.10 U4.J13 | length 267.4
  Top Layer w3.5: 2318,1735 2318,1710.7 U4.J13
  Top Layer w5: J2.10 2182,1828 2225,1785 2299,1785 2318,1766 2318,1735
GPIO22: J2.9 U4.H12 | length 352
  Top Layer w3.5: 2290,1740 2290,1735 2298,1727 2298,1693.96 2307.8,1684.16 U4.H12
  Top Layer w5: J2.9 2080,1828 2133,1775 2263,1775 2290,1748 2290,1740
GPIO23: J2.8 U4.G14 | length 393.3
  Top Layer w3.5: 2265,1750 2265,1744.02 U4.G14
  Top Layer w5: J2.8 1981,1828 2044,1765 2254,1765 2265,1754 2265,1750
GPIO24: J2.7 U4.G13 | length 581.4
  Top Layer w3.5: U4.G13 2288.11,1694.66 2298,1684.77 v2(2298,1672)
  Signal Layer 2 w5: J2.7 1888.5,1784.5 2237.5,1784.5 2265,1757 2265,1743 2291,1717 2291,1679 v2(2298,1672)
GPIO25: J2.6 U4.F14 | length 597.5
  Top Layer w3.5: 2255,1734.33 U4.F14
  Top Layer w5: v1(2246,1750) 2246,1743.33 2255,1734.33
  Signal Layer 2 w5: J2.6 1745,1792 1762.5,1774.5 2229.5,1774.5 2246,1758 v1(2246,1750)
GPIO26: J2.5 U4.F13 | length 730.4
  Top Layer w5: U4.F13 2278,1710.8 v2(2278,1711)
  Signal Layer 2 w5: J2.5 1645,1788 1668.5,1764.5 2220.5,1764.5 2230,1755 2230,1735 2235,1730 2250,1730 2269,1711 v2(2278,1711)
GPIO27: J2.4 U4.G12 | length 848.4
  Top Layer w5: v2(2279,1672) 2288.11,1681.11 U4.G12
  Signal Layer 2 w5: J2.4 1545,1780 1571,1754 2190,1754 2202.5,1741.5 2202.5,1741.24 2224.74,1719 2246,1719 2269,1696 2269,1682 v2(2279,1672)
GPIO28: J2.3 U4.F12 | length 927.2
  Top Layer w5: v2(2260,1672) 2268.43,1680.43 U4.F12
  Signal Layer 2 w5: J2.3 1445,1787 1489,1743 2185,1743 2220,1708 2242,1708 2253,1697 2253,1679 v2(2260,1672)
GPIO29: J2.2 U4.E12 | length 1002.6
  Top Layer w5: v2(2240,1672) 2248.74,1680.74 U4.E12
  Signal Layer 2 w5: J2.2 1345,1777 1350,1772 1436,1772 1476,1732 2180,1732 v2(2240,1672)
INITN: R14.2 U4.B13 | length 39.9
  Top Layer w3.5: v2(2179.91,1711) U4.B13
  Bottom Layer w5: v2(2179.91,1711) 2179.91,1705.09 2189.62,1695.38 R14.2
KEY1: K1.1 R28.1 U4.L14 | length 773.6
  Top Layer w3.5: U4.L14 2366.85,1735
  Top Layer w5: 2366.85,1735 2366.85,1754.85 2385,1773 2942,1773 K1.1 v1(3035,1715)
  Bottom Layer w5: v1(3035,1715) R28.1
KEY2: K2.1 R29.1 U4.M13 | length 885.8
  Top Layer w3.5: 2377,1735 2377,1710.76 U4.M13
  Top Layer w5: 2377,1735 2377,1743 2397,1763 2933,1763 2971.51,1724.49 2971.51,1667.49 3000,1639 K2.1 v1(3035,1590)
  Bottom Layer w5: v1(3035,1590) R29.1
KEY3: K3.1 R30.1 U4.M14 | length 952.6
  Top Layer w3.5: U4.M14 2386.54,1729.54 2399,1742
  Top Layer w5: 2399,1742 2410,1753 2928,1753 2961,1720 2961,1554 3000,1515 K3.1 v1(3035,1465)
  Bottom Layer w5: v1(3035,1465) R30.1
KEY4: K4.1 R31.1 U4.N14 | length 1039.2
  Top Layer w3.5: U4.N14 2406.22,1727.22 2416,1737
  Top Layer w5: 2416,1737 2422,1743 2922.5,1743 2951,1714.5 2951,1439 3000,1390 K4.1 v1(3035,1340)
  Bottom Layer w5: v1(3035,1340) R31.1
LED1: LD1.2 U4.N13 | length 192.8
  Top Layer w3.5: U4.N13 2416,1711 2441,1711
  Top Layer w5: 2441,1711 2476,1711 2490,1725 2525,1725 2535,1715 LD1.2
LED2: LD2.2 U4.M12 | length 215.2
  Top Layer w3.5: U4.M12 2396,1691 2440,1691
  Top Layer w5: 2440,1691 2554,1691 LD2.2
LED3: LD3.2 U4.P12 | length 208.4
  Top Layer w3.5: U4.P12 2440,1681.54
  Top Layer w5: 2440,1681.54 2538.46,1681.54 2555,1665 2555,1635 LD3.2
LED4: LD4.2 U4.M11 | length 291.8
  Top Layer w3.5: U4.M11 2386.54,1662.75 2394,1662.75 2403.25,1672 2440,1672
  Top Layer w5: 2440,1672 2528,1672 2545,1655 2545,1625 2555,1615 2555,1580 LD4.2
LED5: LD5.2 U4.P11 | length 286.8
  Top Layer w3.5: U4.P11 2440.03,1661.85
  Top Layer w5: 2440.03,1661.85 2518.15,1661.85 2535,1645 2535,1615 2545,1605 2545,1570 2555,1560 2555,1525 LD5.2
LED6: LD6.2 U4.N10 | length 351.4
  Top Layer w3.5: U4.N10 2416.05,1652 2432,1652 2434,1654 2448,1654 2450,1652
  Top Layer w5: 2450,1652 2508,1652 2525,1635 2525,1605 2535,1595 2535,1560 2545,1550 2545,1515 2555,1505 2555,1470 LD6.2
LED7: LD7.2 U4.N9 | length 392.9
  Top Layer w3.5: U4.N9 2415.74,1632 2432,1632 2434,1630 2448,1630 2458,1640
  Top Layer w5: 2458,1640 2500,1640 2515,1625 2515,1595 2525,1585 2525,1550 2535,1540 2535,1505 2545,1495 2545,1460 2555,1450 2555,1415 LD7.2
LED8: LD8.2 U4.P9 | length 396.8
  Top Layer w3.5: U4.P9 2450,1622.48
  Top Layer w5: 2450,1622.48 2491.52,1622.48 2505,1609 2505,1585 2515,1575 2515,1540 2525,1530 2525,1495 2535,1485 2535,1450 2545,1440 2545,1405 2555,1395 2555,1360 LD8.2
NetC1_1: C1.1 C2.1 L1.2 U1.3 | length 389
  Bottom Layer w5: L1.2 1398,1478 1508,1478 1520,1466 1520,1456 C1.1 1554,1422 C2.1 1603,1422 1627.37,1446.37 U1.3
NetC3_1: C3.1 C4.1 L2.1 U1.8 | length 182.8
  Bottom Layer w5: L2.1 1554,1521 C3.1 1609,1540 C4.1 1611.2,1544.8 U1.8
NetC11_1: C11.1 U1.38 | length 191.1
  Bottom Layer w5: U1.38 1963.84,1311.16 1974,1301 2074,1301 C11.1
NetC12_1: C12.1 U1.37 | length 130.9
  Bottom Layer w5: U1.37 1983.53,1317.47 1987,1314 2061,1314 C12.1
NetC13_1: C13.1 L3.1 | length 57
  Top Layer w10: L3.1 1320,1753 C13.1
NetD1_2: D1.2 J1.2 U1.6 | length 404.8
  Top Layer w8: J1.2 1396.06,1551.06 1410,1565 D1.2 1440,1565 1450,1555 1605,1555 v6(1655,1505)
  Bottom Layer w8: v6(1655,1505) 1655.42,1505.42 U1.6
NetD2_2: D2.2 J1.3 U1.7 | length 415.7
  Top Layer w8: J1.3 1389.53,1525.47 1405,1510 D2.2 1460,1540 1587,1540 v6(1622,1505)
  Bottom Layer w8: v6(1622,1505) 1642.11,1525.11 U1.7
NetLD1_1: LD1.1 R25.1 | length 54
  Top Layer w5: LD1.1 v1(2680,1715)
  Bottom Layer w5: v1(2680,1715) R25.1
NetLD2_1: LD2.1 R26.1 | length 54
  Top Layer w5: LD2.1 v1(2680,1660)
  Bottom Layer w5: v1(2680,1660) R26.1
NetLD3_1: LD3.1 R32.1 | length 54
  Top Layer w5: LD3.1 v1(2680,1605)
  Bottom Layer w5: v1(2680,1605) R32.1
NetLD4_1: LD4.1 R33.1 | length 54
  Top Layer w5: LD4.1 v1(2680,1550)
  Bottom Layer w5: v1(2680,1550) R33.1
NetLD5_1: LD5.1 R35.1 | length 54
  Top Layer w5: LD5.1 v1(2680,1495)
  Bottom Layer w5: v1(2680,1495) R35.1
NetLD6_1: LD6.1 R36.1 | length 54
  Top Layer w5: LD6.1 v1(2680,1440)
  Bottom Layer w5: v1(2680,1440) R36.1
NetLD7_1: LD7.1 R38.1 | length 54
  Top Layer w5: LD7.1 v1(2680,1385)
  Bottom Layer w5: v1(2680,1385) R38.1
NetLD8_1: LD8.1 R40.1 | length 54
  Top Layer w5: LD8.1 v1(2680,1330)
  Bottom Layer w5: v1(2680,1330) R40.1
NetLD9_1: LD9.1 R12.1 | length 50
  Top Layer w10: R12.1 LD9.1@1309,1300
NetLED1_1: LED1.1 R39.1 | length 106.4
  Top Layer w5: LED1.1 2217,1358 R39.1
NetLED1_2: LED1.2 R34.1 | length 39
  Top Layer w5: LED1.2 2256.06,1328 R34.1
NetLED1_4: LED1.4 R37.1 | length 35.4
  Top Layer w5: LED1.4 R37.1@2286.46,1299.54
NetLED2_1: LED2.1 R27.1 | length 106.4
  Top Layer w5: LED2.1 2396,1358 R27.1
NetLED2_2: LED2.2 R23.1 | length 39
  Top Layer w5: LED2.2 2435.06,1328 R23.1
NetLED2_4: LED2.4 R24.1 | length 35.4
  Top Layer w5: LED2.4 R24.1@2465.46,1299.54
NetR5_1: R5.1 U1.34 | length 65.2
  Bottom Layer w5: U1.34 2095.63,1446.37 R5.1@2107,1435
NetR6_1: R6.1 R9.1 U2.1 | length 90.2
  Bottom Layer w5: U2.1@2335,1374.99 2356.01,1374.99 2371,1360 R6.1 R9.1
NetR7_1: R7.1 U1.44 U2.4 | length 458.5
  Bottom Layer w5: U1.44 1845.73,1313.27 1871,1288 2089,1288 2131,1330 R7.1 2151.09,1332 2184.09,1299 U2.4@2230,1299
NetR8_1: R8.1 U1.45 U2.5 | length 635.8
  Bottom Layer w5: U1.45 1826.05,1309.95 1861,1275 2252,1275 2266,1289 2266,1327 2246,1347 U2.5 2208,1347 2193,1332 R8.1
NetR9_2: R9.2 U1.43 U2.3 | length 697.9
  Bottom Layer w5: U1.43 1865.42,1401.42 1899,1435 1967,1435 2009,1393 2099,1393 2107,1401 2185,1401 2193,1409 2260,1409 2270,1399 2270,1343.75 2304.75,1309 2325,1309 U2.3@2335,1299 ; U2.3 R9.2@2390,1309
NetR10_2: R10.2 U1.5 | length 96.5
  Bottom Layer w5: R10.2 1641,1471 1655.74,1485.74 U1.5
PCLK: R11.1 U4.C1 | length 631.9
  Top Layer w3.5: v1(2209,1451) 2209.37,1451.37 U4.C1
  Signal Layer 1 w5: v1(1652,1393) 1664,1381 2139,1381 v1(2209,1451)
  Bottom Layer w5: R11.1 1628,1393 v1(1652,1393)
PROGRAM: R15.2 U4.C10 | length 64.7
  Top Layer w5: U4.C10 2226,1625.54 v1(2226,1612)
  Bottom Layer w5: R15.2 2224.38,1612 v1(2226,1612)
R_LED1: R39.2 U4.M2 | length 188.4
  Top Layer w3.5: U4.M2 2396,1475.22 2396,1454
  Top Layer w5: R39.2 2311.62,1359.62 2348,1396 2387,1396 2396,1405 2396,1454
R_LED2: R27.2 U4.M3 | length 226.3
  Top Layer w3.5: U4.M3 2396.91,1494 2434,1494 2443,1485 2449,1485
  Top Layer w5: 2449,1485 2464,1485 2494,1455 2494,1361.38 R27.2
SCL: J3.2 R18.2 U4.C8 | length 1147.7
  Top Layer w3.5: v2(2200,1612.17) U4.C8
  Signal Layer 2 w5: J3.2 1437,1320 1920,1320 1946,1346 1946,1378 2009,1441 2172,1441 2177,1446 2177,1589.17 v2(2200,1612.17)
  Bottom Layer w5: R18.2 2199.17,1613 v2(2200,1612.17)
SDA: J3.3 R17.2 U4.B8 | length 1069.1
  Top Layer w3.5: U4.B8 2190.2,1602.8 v2(2200,1593)
  Signal Layer 2 w5: J3.3 1445,1274 1481,1310 1930,1310 1956,1336 1956,1373 2014,1431 2176,1431 2187,1442 2187,1580 v2(2200,1593)
  Bottom Layer w5: R17.2 2196,1589 v2(2200,1593)
SEG-A1: DISP1.17 U4.A10 | length 577.5
  Top Layer w3.5: 2155,1642.17 U4.A10
  Top Layer w5: DISP1.17 1670.08,1665.92 1709,1627 1890,1627 1902,1615 2075,1615 2102.17,1642.17 2155,1642.17
SEG-A2: DISP1.12 U4.C12 | length 301.2
  Top Layer w3.5: 2155,1691 2199.91,1691 U4.C12
  Top Layer w5: DISP1.12 1953.54,1691.46 1980,1665 2050,1665 2076,1691 2155,1691
SEG-B1: DISP1.16 U4.C11 | length 544
  Top Layer w3.5: 2155,1652 2192.95,1652 2202.81,1661.85 U4.C11
  Top Layer w5: DISP1.16 1726.77,1693.23 1783,1637 1897,1637 1909,1625 2070,1625 2097,1652 2155,1652
SEG-B2: DISP1.11 U4.B14 | length 191.9
  Top Layer w5: DISP1.11 2030.09,1731 2179.59,1731 2185.5,1725.09 U4.B14
SEG-C1: DISP1.4 U4.F2 | length 734.6
  Top Layer w3.5: 2252,1442 2259,1449 2259,1475.26 U4.F2
  Top Layer w5: DISP1.4 1670.08,1410.08 1715,1455 2085,1455 2115,1425 2235,1425 2252,1442
SEG-C2: DISP1.9 U4.J1 | length 486
  Top Layer w3.5: 2327.48,1450 U4.J1
  Top Layer w5: DISP1.9 1953.54,1390.54 1978,1415 2045,1415 2075,1385 2266,1385 2327.48,1446.48 2327.48,1450
SEG-D1: DISP1.2 U4.E1 | length 814.4
  Top Layer w3.5: 2243,1448 2248.74,1453.74 U4.E1
  Top Layer w5: DISP1.2 1556.69,1416.69 1605,1465 2095,1465 2124,1436 2231,1436 2243,1448
SEG-D2: DISP1.7 U4.H1 | length 582.8
  Top Layer w3.5: 2307.8,1450 U4.H1
  Top Layer w5: DISP1.7 1840.16,1395.16 1870,1425 2055,1425 2085,1395 2257,1395 2307.8,1445.8 2307.8,1450
SEG-DIG1: DISP1.3 DISP1.18 U4.C9 | length 1019.2
  Top Layer w3.5: 2155,1632 2199.85,1632 U4.C9
  Top Layer w5: DISP1.3@1615.39,1330 1615.39,1395.39 1638,1418 v1(1638,1430) ; DISP1.18@1615.39,1723.7 1615.39,1676.61 v1(1638,1654) 1675,1617 1884,1617 1896,1605 2080,1605 2107,1632 2155,1632
  Signal Layer 1 w5: v1(1638,1430) v1(1638,1654)
SEG-DIG2: DISP1.8 DISP1.13 U4.A12 | length 891.8
  Top Layer w3.5: 2155,1681.54 U4.A12
  Top Layer w5: v1(1885,1397) 1885,1343.85 DISP1.8@1898.85,1330 ; v1(1909,1798) 1909,1796.3 1898.85,1786.15 1898.85,1691.15 1935,1655 2055,1655 2081.54,1681.54 2155,1681.54
  Signal Layer 1 w5: v1(1885,1397) 1885,1774 v1(1909,1798)
SEG-DP1: DISP1.5 U4.F1 | length 662.1
  Top Layer w3.5: 2268.43,1450 U4.F1
  Top Layer w5: DISP1.5 1726.77,1401.77 1770,1445 2075,1445 2105,1415 2240,1415 2268.43,1443.43 2268.43,1450
SEG-DP2: DISP1.10 U4.K1 | length 397.7
  Top Layer w3.5: 2347.17,1450 U4.K1
  Top Layer w5: DISP1.10 2040.24,1375 2276,1375 2347.17,1446.17 2347.17,1450
SEG-E1: DISP1.1 U4.E2 | length 847.6
  Top Layer w3.5: 2158,1475 2239.05,1475 U4.E2
  Top Layer w5: DISP1.1 1500,1415 1560,1475 2158,1475
SEG-E2: DISP1.6 U4.H2 | length 650.6
  Top Layer w3.5: 2294,1450 2298,1454 2298,1474.89 U4.H2
  Top Layer w5: DISP1.6 1783.46,1398.46 1820,1435 2065,1435 2095,1405 2249,1405 2294,1450
SEG-F1: DISP1.19 U4.A9 | length 683.2
  Top Layer w3.5: 2155,1622.48 U4.A9
  Top Layer w5: DISP1.19 1556.69,1693.31 1644,1606 1878,1606 1889,1595 2086,1595 2113.48,1622.48 2155,1622.48
SEG-F2: DISP1.14 U4.B12 | length 401.6
  Top Layer w3.5: 2155,1672 2180.15,1672 U4.B12
  Top Layer w5: DISP1.14 1840.16,1694.84 1874,1661 1909,1661 1925,1645 2060,1645 2087,1672 2155,1672
SEG-G1: DISP1.20 U4.B9 | length 766.9
  Top Layer w3.5: 2156,1613 2180.2,1613 U4.B9
  Top Layer w5: DISP1.20 1500,1695 1600,1595 1871,1595 1881,1585 2095.52,1585 2123.52,1613 2156,1613
SEG-G2: DISP1.15 U4.A11 | length 440.7
  Top Layer w3.5: 2155,1661.85 U4.A11
  Top Layer w5: DISP1.15 1783.46,1691.54 1827,1648 1903,1648 1916,1635 2065,1635 2091.85,1661.85 2155,1661.85
SN: R16.2 U4.N12 | length 75.9
  Top Layer w3.5: v2(2376,1671) 2377.26,1672.26 2390.38,1672.26 2399.66,1681.54 U4.N12
  Bottom Layer w3.5: v2(2376,1671) 2381.62,1676.62 R16.2
SPICS: J2.16 U4.P3 | length 628
  Top Layer w3.5: U4.P3 v1@2441.63,1504.37
  Signal Layer 1 w5: v1(2443,1502) 2459,1502 2476.86,1519.86 2476.86,1576.77 2477.5,1577.41 2477.5,1588.59 2476.86,1589.23 2476.86,1590 2476.72,1590 2465,1601.72 2465,1746.28 2494.72,1776 2736,1776 2745,1785 J2.16
SPISCK: J2.17 U4.M4 | length 818.4
  Top Layer w5: U4.M4 v2(2396,1533.52)
  Signal Layer 1 w5: v2(2396,1533.52) 2404.48,1533.52 2412,1526 2412,1498 2426,1484 2458,1484 2490,1516 2490,1591 2481,1600 2480.86,1600 2475,1605.86 2475,1742.14 2498.86,1766 2822,1766 2845,1789 J2.17
SPISI: J2.19 U4.P13 | length 710.9
  Top Layer w3.5: U4.P13 2440,1701.22
  Top Layer w5: 2440,1701.22 2497.22,1701.22 v1(2505,1709)
  Signal Layer 1 w5: v1(2505,1709) 2505,1729 2520,1744 3008,1744 3045,1781 J2.19
SPISO: J2.18 U4.N4 | length 919.4
  Top Layer w5: v2(2396.94,1514.78) U4.N4
  Signal Layer 1 w5: v2(2396.94,1514.78) 2396.94,1497.06 2420,1474 2464,1474 2501,1511 2501,1594.14 2485,1610.14 2485,1737.86 2502,1754.86 2502,1755 2921,1755 2945,1779 J2.18
SW1: R19.2 SW1.1 U4.M7 | length 622.4
  Top Layer w5: v1(2361,1589) 2380.65,1589 U4.M7 ; SW1.1 v1(2755,1430)
  Bottom Layer w5: v1(2361,1589) 2401,1589 2412,1578 2447,1578 2455.5,1569.5 2471.5,1569.5 2493,1591 2521,1591 2535,1577 2535,1527 2584,1478 2726,1478 2755,1449 v1(2755,1430) R19.2
SW2: R20.2 SW1.2 U4.M8 | length 659.4
  Top Layer w5: v2(2370,1606) 2373.2,1602.8 U4.M8 ; SW1.2 v1(2805,1430)
  Bottom Layer w5: v2(2370,1606) 2384,1606 2392,1598 2403,1598 2411,1606 2423,1606 2428,1601 2428,1597 2437,1588 2446,1588 2459,1601 2530,1601 2545,1586 2545,1555 2578,1522 2746,1522 2805,1463 v1(2805,1430) R20.2
SW3: R21.2 SW1.3 U4.M9 | length 709.9
  Top Layer w3.5: v1(2361.48,1622.48) 2363.96,1620 2372.01,1620 2374.01,1618 2382.06,1618 U4.M9
  Top Layer w5: SW1.3 v1(2855,1430)
  Bottom Layer w5: v1(2361.48,1622.48) 2364.96,1619 2383,1619 2392,1628 2411,1628 2420,1619 2532,1619 2573,1578 2748,1578 2855,1471 v1(2855,1430) R21.2
SW4: R22.2 SW1.4 U4.M10 | length 737.1
  Top Layer w5: v2(2376.37,1632) U4.M10 ; SW1.4 v1(2905,1430)
  Bottom Layer w5: v2(2376.37,1632) 2383.37,1639 2416,1639 2426,1629 2552,1629 2555,1632 2747,1632 2905,1474 v1(2905,1430) R22.2
TCK: R1.2 U1.13 U4.B6 | length 608
  Top Layer w3.5: 2146.32,1554 2180.26,1554 U4.B6
  Top Layer w5: v1(1767,1578) 1767,1575 1775,1567 1820,1567 1833,1554 2146.32,1554
  Bottom Layer w5: R1.2 1759,1723 1766.99,1715.01 U1.13 1766.99,1575.01 v1(1767,1578)
TDI: R4.1 U1.14 U4.B4 | length 609.8
  Top Layer w3.5: 2155,1514 2179.63,1514 U4.B4
  Top Layer w5: v1(1787,1552) 1805,1534 2109,1534 2129,1514 2155,1514
  Bottom Layer w5: R4.1 1784,1725 1786.68,1722.32 U1.14 1787,1686.2 v1(1787,1552)
TDO: R3.1 U1.15 U4.A4 | length 557.5
  Top Layer w3.5: 2155,1524.06 U4.A4
  Top Layer w5: v1(1813,1552) 1821,1544 2115,1544 2134.94,1524.06 2155,1524.06
  Bottom Layer w5: U1.15 1806.36,1735.36 R3.1 ; U1.15@1807,1685.89 1807,1558 v1(1813,1552)
TMS: R2.1 U1.16 U4.A6 | length 507.2
  Top Layer w3.5: 2148,1563.43 U4.A6
  Top Layer w5: v1(1836,1578) 1850,1564 2148,1564
  Bottom Layer w5: R2.1 1834,1730 1826.05,1722.05 U1.16 1826.05,1587.95 v1(1836,1578)
VBUS: C21.1 J1.1 J2.1 L3.2 U3.3 | length 695.4
  Top Layer w15: 1288,1600 J1.1@1311.35,1576.65 ; J1.1 1371.65,1576.65 v8(1380,1585)
  Top Layer w20: J2.1 1248,1825 L3.2 1248,1728 1282,1694 1282,1606 1288,1600
  Bottom Layer w15: J2.1@1245,1825 J2.1 ; C21.1 1380,1646 v8(1380,1585) 1401.14,1585 1400.94,1585.2 U3.3
  Bottom Layer w20: J2.1@1248,1825 1248,1737 1317,1668 C21.1
  other v7: 1380,1621
pads on no net: J1. J1.4 SW1.9 U1.2 U1.17 U1.18 U1.19 U1.20 U1.21 U1.25 U1.26 U1.27 U1.28 U1.29 U1.30 U1.31 U1.32 U1.33 U4.A2 U4.A3 U4.A7 U4.B1 U4.B2 U4.B3 U4.B5 U4.B7 U4.C2 U4.C3 U4.C4 U4.C6 U4.C7 U4.C13 U4.C14 U4.D1 U4.D12 U4.E13 U4.E14 U4.M1 U4.M5 X1.1
copper on no net:
  other v5: 1330,1430 1330,1620.94

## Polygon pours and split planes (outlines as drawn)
GND on Signal Layer 1 "signal layer 1-GND" (solid, remove dead copper, shelved, pour order 4): 1173,1886 1173,1170 3216,1170 3216,1886
GND on Top Layer "TOP-GND" (solid, remove dead copper, shelved, pour order 10): 3216,1886 3020,1886 3020,1170 3216,1170
GND on Top Layer "TOP-GND" (solid, remove dead copper, shelved, pour order 12): 2170,1720.91 2170,1465 2425.91,1465 2425.91,1720.91
GND on Bottom Layer "BTM-GND" (solid, remove dead copper, shelved, pour order 8): 1173,1886 1173,1170 3216,1170 3216,1886
+3.3V on Signal Layer 2 "signal layer 2 -3.3V" (solid, remove dead copper, shelved, pour order 2): 1173,1170 3216,1170 3216,1886 1173,1886

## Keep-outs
Keep-Out Layer:
  the board outline again, w2

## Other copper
Top Layer:
  rectangle net GND: 3091,1758.46 3198.98,1877
  rectangle net GND: 3095,1180 3189,1309
  rectangle net GND: 2246,1558 2309,1651
  region net GND: 1258,1467 1250,1475 1187,1475 1178,1484 1178,1568 1186,1576 1287,1576 1293,1570 1293,1467
  region net VBUS: 1350,1583 1370,1603 1370,1637 1373,1640 1388,1640 1393,1635 1393,1575 1387,1569 1350,1569
Signal Layer 1:
  rectangle net GND: 1897.5,1408 1930,1424.86
  rectangle net GND: 1897,1393 1921,1411
  pour cut-out: 2364.62,1555.28 2373.06,1555.28 2374.33,1554.01 2374.33,1542.33 2373,1541 2364.94,1541 2364.87,1540.93
  region net GND: 1915.92,1528.5 1915.92,1524.92 1913,1522 1909,1519 1905,1518 1949,1517 1951.04,1526.33
Signal Layer 2:
  rectangle net +3.3V: 2102,1450 2155,1478
  rectangle net +3.3V: 2197,1632 2244,1658
  rectangle net +3.3V: 1196,1230 1292,1276
  pour cut-out: 2456,1656 2456,1638 2561,1638 2556,1645 2556,1660
  region net +3.3V: 1745,1874 1787,1842 1804,1842 1842,1874
Bottom Layer:
  rectangle net GND: 1364,1397 1393,1471
  rectangle net GND: 2233.91,1687.28 2257.64,1711.28
  rectangle net GND: 1524.78,1554 1585,1665.99
  rectangle net GND: 1177.49,1466 1310,1603.15
  pour cut-out: 1743.09,1777.91 1743,1778 1743,1793 1744,1793 1744,1778
  pour cut-out: 1845,1793.17 1845,1772.62 1844.38,1772 1844,1772 1844,1793
  pour cut-out: 1365.7,1562.7 1366,1562.41 1366,1528 1368,1528 1368,1560
  pour cut-out: 1502.5,1529.5 1521.5,1529.5 1522,1529 1522,1528 1502,1528
  pour cut-out: 1406,1432 1358,1375 1358,1299 1507,1299 1504.69,1301.31 1504.69,1488.5
  region net GND: 2019.69,1321.65 2053.65,1321.65 2063.09,1331.09 2063.09,1364.73 2022.73,1364.73 2020,1362
  pour cut-out: 2870.91,1385 2870.91,1364.09 2889.09,1364.09 2889.09,1385
  pour cut-out: 2820.91,1385 2820.91,1364.09 2839.09,1364.09 2839.09,1385
  pour cut-out: 2770.91,1364.09 2770.91,1385 2789.09,1385 2789.09,1364.09
  pour cut-out: 2342.28,1554.09 2331.38,1549.09 2329,1533 2320,1525 2370.5,1522 2370.5,1543.37 2359.77,1554.09
  pour cut-out: 2358,1517 2373,1502 2373,1483 2377,1483 2379,1485 2379,1486.29 2382.78,1490.07 2382.78,1498.51 2390.28,1506 2390.28,1519.72 2383,1527
  pour cut-out: 1799.28,1284.09 1799.28,1249.09 1811.36,1237.01 1833.35,1259 1856,1259 1856,1278 1831,1303
  region net GND: 1900,1400 1900,1420 1907.35,1427.35 1927.34,1427.35 1927.34,1420.34 1924,1417
  region net +3.3V: 1395,1762 1470,1762 1473,1760 1473,1689 1442,1658 1421,1658 1395,1679
  region net VBUS: 1379,1554 1368,1565 1368,1676 1372,1680 1386,1680 1379,1680 1400,1657 1400,1648 1432,1616 1432,1554

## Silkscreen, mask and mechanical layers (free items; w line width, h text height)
Top Overlay:
  text "SI" at 3008,1812 h40 r90
  text "SO" at 2908,1806 h40 r90
  text "CS" at 2708,1805 h40 r90
  text "SCK" at 2808,1796 h40 r90
  text "GND" at 3108,1792 h40 r90
  text "29" at 1280,1785 h40
  text "28" at 1376,1785 h40
  text "27" at 1475.39,1785 h40
  text "26" at 1575.59,1785 h40
  text "25" at 1675.79,1785 h40
  text "24" at 1775.99,1785 h40
  text "23" at 1876.18,1785 h40
  text "22" at 1976.38,1785 h40
  text "21" at 2076.58,1785 h40
  text "20" at 2176.78,1785 h40
  text "19" at 2277.01,1785 h40
  text "18" at 2377.21,1785 h40
  text "17" at 2476,1785 h40
  text "16" at 2577.61,1785 h40
  text "VBUS" at 1204,1780 h40 r90
  text "V2.2" at 2738,1288 h60
  text "1" at 1588,1244 h40
  text "2" at 1685,1244 h40
  text "3" at 1785,1244 h40
  text "4" at 1884,1244 h40
  text "5" at 1984,1244 h40
  text "6" at 2085,1244 h40
  text "7" at 2185,1244 h40
  text "8" at 2286,1244 h40
  text "9" at 2386,1244 h40
  text "10" at 2475,1244 h40
  text "11" at 2576,1244 h40
  text "12" at 2674,1244 h40
  text "13" at 2774,1244 h40
  text "14" at 2875,1244 h40
  text "15" at 2976,1244 h40
  text "0" at 1486,1242 h40
  text "3.3V" at 1204,1196 h40 r90
  text "SCL" at 1307,1193 h40 r90
  text "SDA" at 1408,1192 h40 r90
  text "GND" at 3109,1190 h40 r90
Bottom Overlay:
  text "STEP" at 2652,1385 h100
  text "V2.2" at 2653,1301 h80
